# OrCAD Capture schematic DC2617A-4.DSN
size Custom; title: ISO SPI AND ISOLATED CAN ARDUINO BOARD; rev: 4; company: TM
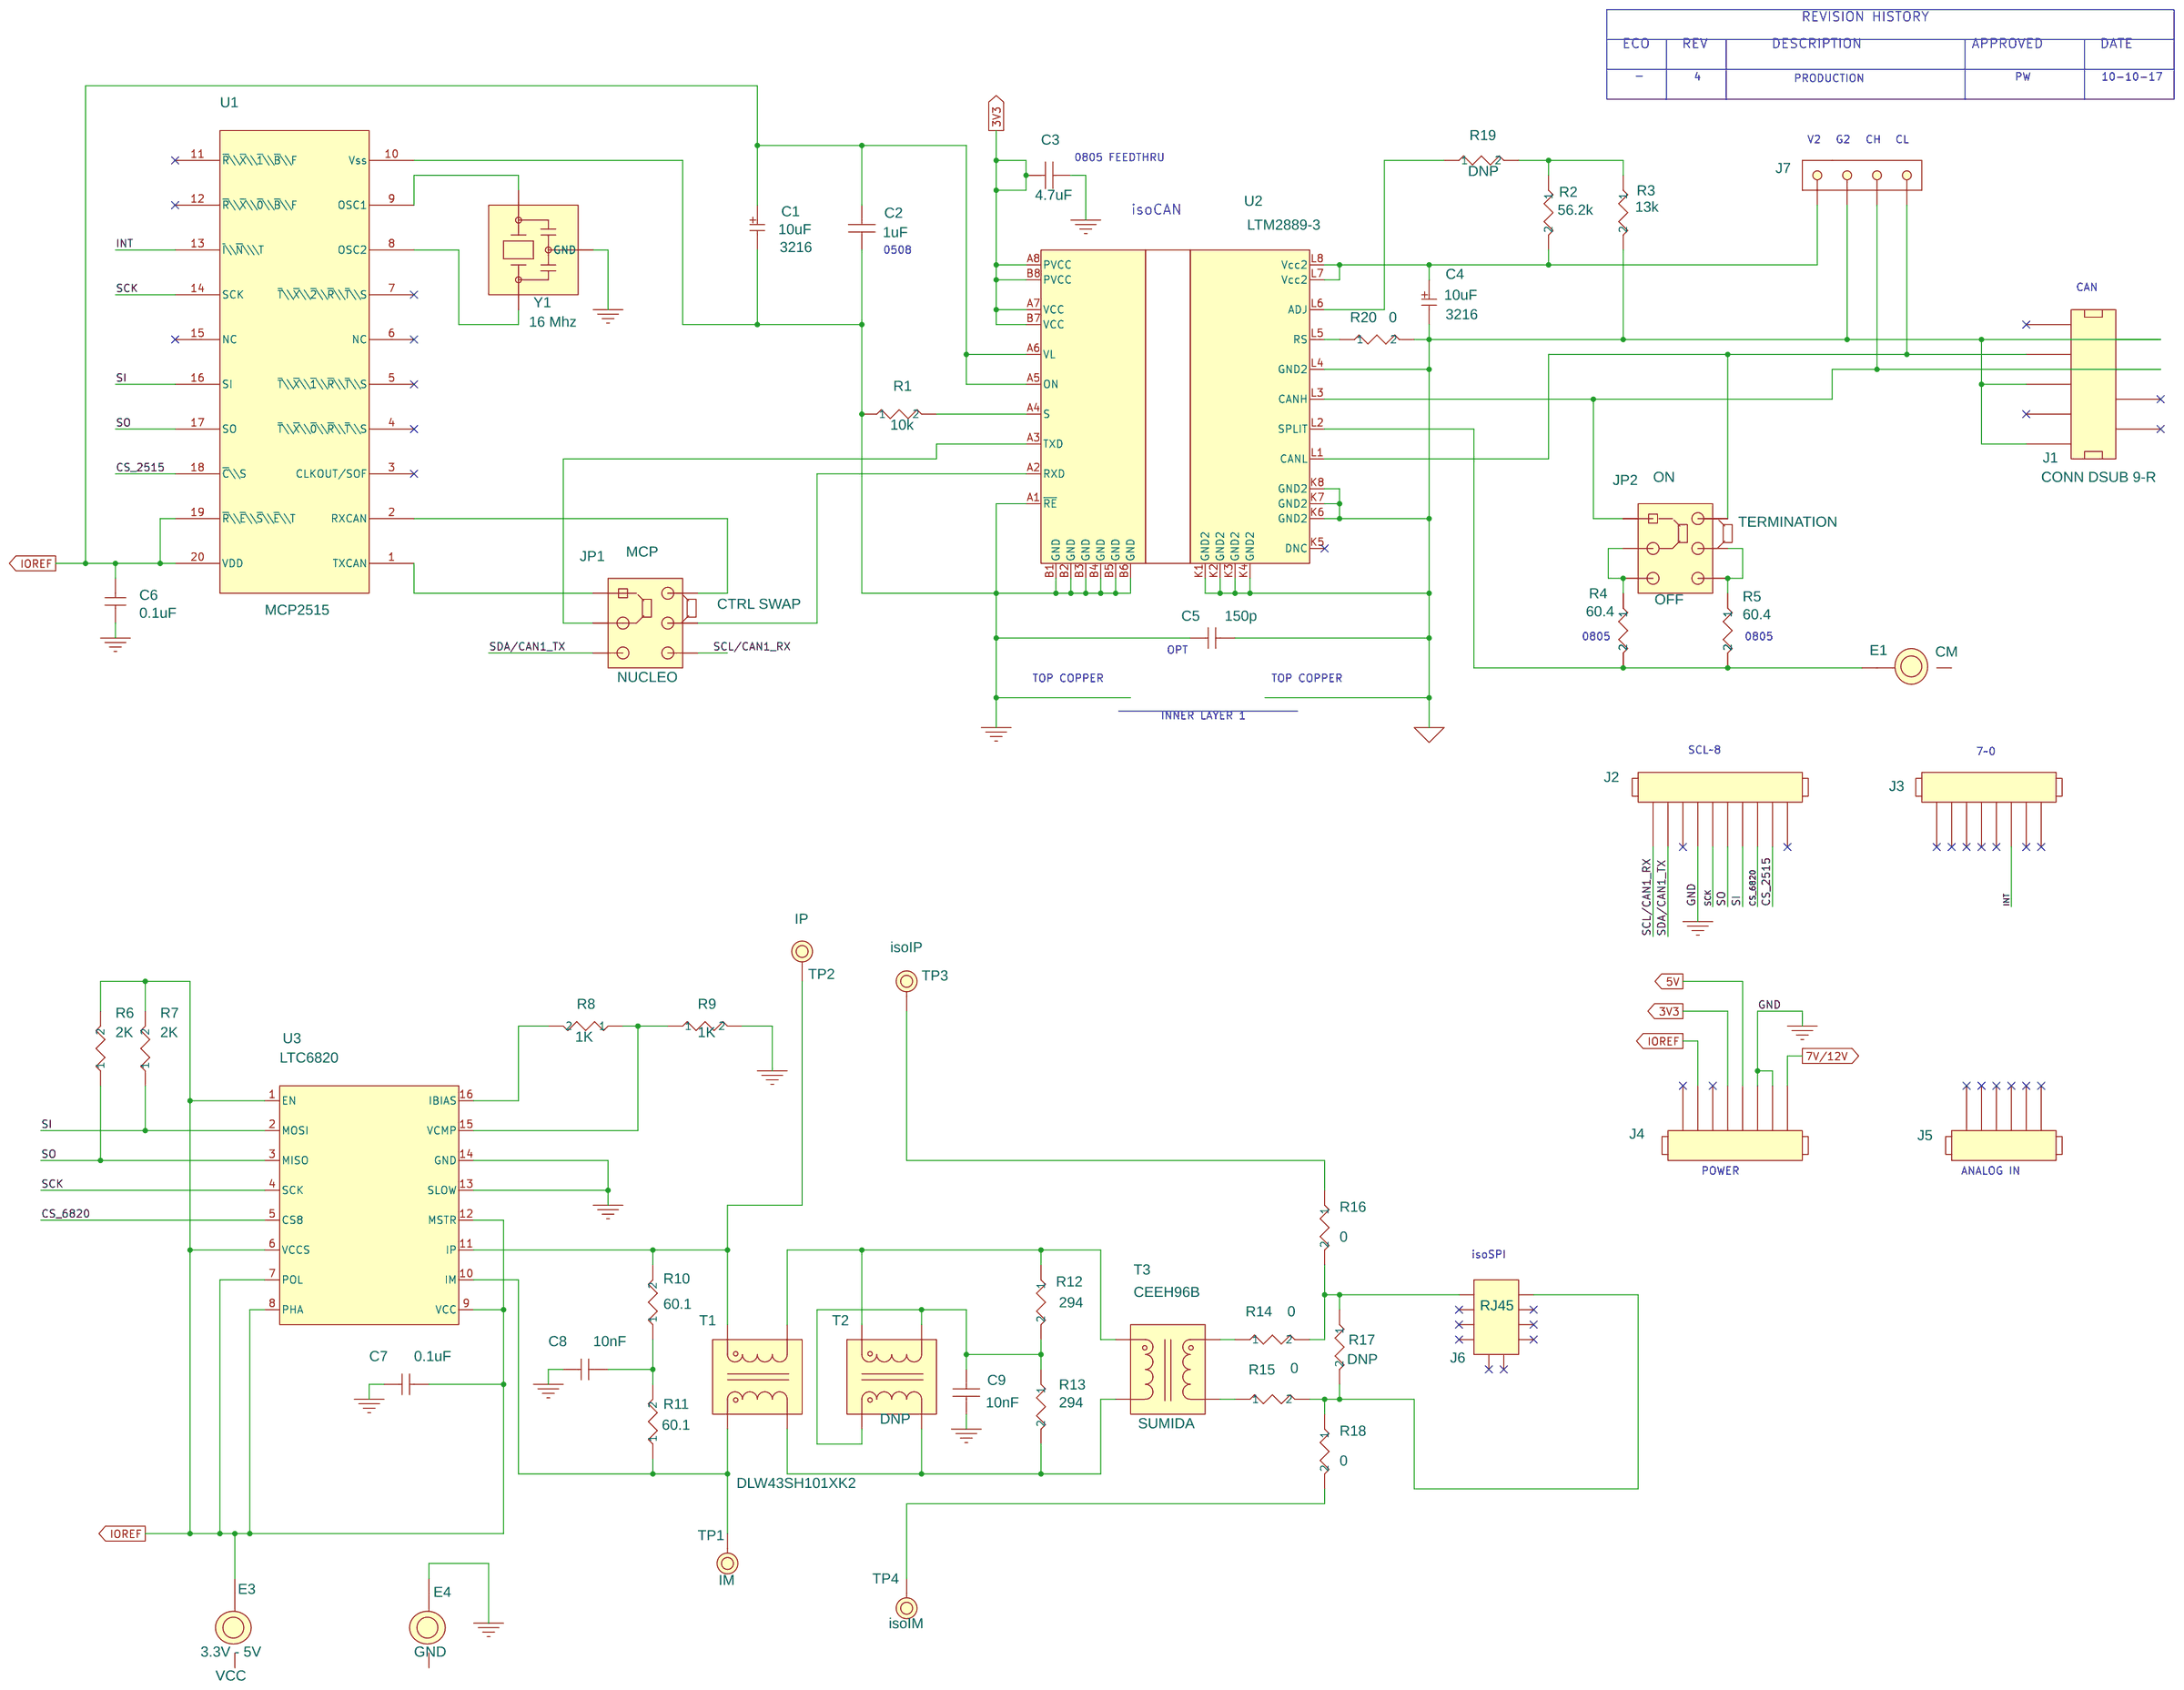
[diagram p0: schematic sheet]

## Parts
C1  10uF  [3216/1206]
C2  1uF  [MURATA-LLL219R71A105MA01L]
C3  4.7uF  [MURATA-NFM21P]
C4  10uF  [3216/1206]
C5  150p  [VISHAY-VY1_SERIES]
C6  0.1uF  [0603]
C7  0.1uF  [0603]
C8  10nF  [0603]
C9  10nF  [0603]
E1  CM  [MILLMAX-2308-2]
E3  VCC  [MILLMAX-2308-2]
E4  GND  [MILLMAX-2308-2]
J1  CONN DSUB 9-R  [CON-D-SUB9-SHIELDED]
J2  SQ POST HEADER SKT 10PIN  [SIP-10P-ARDUINO]
J3  SQ POST HEADER SKT 8PIN  [SIP-8P-ARDUINO]
J4  SQ POST HEADER SKT 8PIN  [SIP-8P-ARDUINO]
J5  SQ POST HEADER SKT 6PIN  [SIP-6P-ARDUINO]
J6  RJ45  [RJ45]
J7  HDR.  [HDR-TSW-104-07-L-S]
JP1  3 Pins 2mm Ctrs.  [HDR2X3-0.1]
JP2  3 Pins 2mm Ctrs.  [HDR2X3-0.1]
R1  10k  [0603]
R2  56.2k  [0603]
R3  13k  [0603]
R4  60.4  [0805]
R5  60.4  [0805]
R6  2K  [0603]
R7  2K  [0603]
R8  1K  [0603]
R9  1K  [0603]
R10  60.1  [0603]
R11  60.1  [0603]
R12  294  [0603]
R13  294  [0603]
R14  0  [0603]
R15  0  [0603]
R16  0  [0603]
R17  DNP  [0603]
R18  0  [0603]
R19  DNP  [0603]
R20  0  [0603]
T1  DLW43SH101XK2  [TRANS-DLW43S]
T2  DNP  [TRANS-DLW43S]
T3  CEEH96B  [TRANS-CEEH96B]
TP1  5019  [TP]
TP2  5019  [TP]
TP3  5019  [TP]
TP4  5019  [TP]
U1  MCP2515  [MICROCHIP-SO20-TSSOP]
U2  LTM2889-3  [LTM-BGA-32-1851]
U3  LTC6820  [MS16]
XJP18  2mm Ctrs.
XJP19  2mm Ctrs.
XJP20  2mm Ctrs.
XJP21  2mm Ctrs.
Y1  16 Mhz  [MURATA-CSTCE]

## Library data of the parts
C1 C4 = C_elect_0: Voltage: 3216
C2 = CAP_NP_1_v2: CAP, 0402 10nF 10% 16V X7R; Part Number: AVX 0402YC103KAT2A
C3 = CAP_NP_0: CAP, 0402 10nF 10% 16V X7R; Part Number: AVX 0402YC103KAT2A
C5-C8 = CAP-NP: CAP, 0603 0.01uF; Part Number: TDK C1608X7R1E104K
C9 = CAP_NP_1: CAP, 0603 100nF 10% 25V X7R; Part Number: MURATA GCM188R71E104KA57D
E1 E4 = E_13
E3 = E_13: VOLTAGE: 3.3V - 5V
J1 = CONN_DSUB_9-R
J2 = SQ_POST_HEADER_SKT_10PIN
J3 J4 = SQ_POST_HEADER_SKT_8PIN
J5 = SQ_POST_HEADER_SKT_6PIN
J6 = HEADER_16_8
J7 = HDR1X4: CONN.,HDR.,MALE,1x4,2.54mm,THT, STR; CLASS: IO; Manufacturer: SAMTEC; Manufacturer PN: TSW-104-07-L-S; PART_NUMBER: 250-0580
JP1 = Commcon2802s03g2_0: 10th Part Field: MCP; 11th Part Field: NUCLEO; 12th Part Field: RUN; 9th Part Field: CTRL SWAP
JP2 = Commcon2802s03g2_0: 10th Part Field: ON; 11th Part Field: OFF; 12th Part Field: RUN; 9th Part Field: TERMINATION
R1 = R_7: RES, 0603 4.99K OHMS  1% 1/10W; 5%: 1%; Part Number: NIC NRC06F4991TRF; Tol: 1%
R2 = R_8: RES, 0603 4.99K OHMS  1% 1/10W; 5%: 1%; Part Number: NIC NRC06F4991TRF; Tol: 1%
R3 = R_19: RES, 0603 4.99K OHMS  1% 1/10W; 5%: 1%; Part Number: NIC NRC06F4991TRF; Tol: 1%
R4 = R_1: RES, 0603 4.99K OHMS  1% 1/10W; 5%: 1%; Part Number: NIC NRC06F4991TRF; Tol: 1%
R5 = R: RES, 0603 4.99K OHMS  1% 1/10W; 5%: 1%; Part Number: NIC NRC06F4991TRF; Tol: 1%
R6 = R_14: RES, 0603 4.99K OHMS  1% 1/10W; 5%: 1%; Part Number: NIC NRC06F4991TRF; Tol: 1%
R7 = R_5: RES, 0603 4.99K OHMS  1% 1/10W; 5%: 1%; Part Number: NIC NRC06F4991TRF; Tol: 1%
R8 = R_16: RES, 0603 4.99K OHMS  1% 1/10W; 5%: 1%; Part Number: NIC NRC06F4991TRF; Tol: 1%
R9 = R_3: RES, 0603 4.99K OHMS  1% 1/10W; 5%: 1%; Part Number: NIC NRC06F4991TRF; Tol: 1%
R10 = R_11: RES, 0603 4.99K OHMS  1% 1/10W; 5%: 1%; Part Number: NIC NRC06F4991TRF; Tol: 1%
R11 = R_12: RES, 0603 4.99K OHMS  1% 1/10W; 5%: 1%; Part Number: NIC NRC06F4991TRF; Tol: 1%
R12 = R_13: RES, 0603 100 OHMS 1% 1/10W; Part Number: NIC NRC06F1000TRF; Tol: 1%
R13 = R_10: RES, 0603 100 OHMS 1% 1/10W; Part Number: NIC NRC06F1000TRF; Tol: 1%
R14 = R_6: RES, 0603 100 OHMS 1% 1/10W; Part Number: NIC NRC06F1000TRF; Tol: 1%
R15 = R_4: RES, 0603 100 OHMS 1% 1/10W; Part Number: NIC NRC06F1000TRF; Tol: 1%
R16 = R_9: RES, 0603 100 OHMS 1% 1/10W; Part Number: NIC NRC06F1000TRF; Tol: 1%
R17 = R_2: RES, 0603 100 OHMS 1% 1/10W; Part Number: NIC NRC06F1000TRF; Tol: 1%
R18 = R_15: RES, 0603 100 OHMS 1% 1/10W; Part Number: NIC NRC06F1000TRF; Tol: 1%
R19 = R_18: RES, 0603 4.99K OHMS  1% 1/10W; 5%: 1%; Part Number: NIC NRC06F4991TRF; Tol: 1%
R20 = R_17: RES, 0603 100 OHMS 1% 1/10W; Part Number: NIC NRC06F1000TRF; Tol: 1%
T1 T2 = TRANS-PA0950_22: 4TH PART FIELD: PULSE,; 5TH PART FIELD: PA08xx; 7TH PART FIELD: TRANS.,
T3 = TRANS-PA0950_10: 4TH PART FIELD: SUMIDA; 5TH PART FIELD: PA08xx; 7TH PART FIELD: TRANS.,
TP1 = TP-GENERIC: PC TEST POINT MINI SMD; CLASS: DISCRETE; Label: IM; Manufacturer: Keystone Electronics; PART_NUMBER: TP2
TP2 = TP-GENERIC: PC TEST POINT MINI SMD; CLASS: DISCRETE; Label: IP; Manufacturer: Keystone Electronics; PART_NUMBER: TMP-1572
TP3 = TP-GENERIC: PC TEST POINT MINI SMD; CLASS: DISCRETE; Label: isoIP; Manufacturer: Keystone Electronics; PART_NUMBER: TMP-1572
TP4 = TP-GENERIC: PC TEST POINT MINI SMD; CLASS: DISCRETE; Label: isoIM; Manufacturer: Keystone Electronics; PART_NUMBER: TP2
U1 = MCP2515_1
U2 = LTM2889CY_4
U3 = LTC6820_0
XJP18-XJP21 = CommconCCIJ2MM-138G
Y1 = 16_MHZ_RESONATOR

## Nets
3V3: C3.1(INPUT) C3.3(OUTPUT) J4.4 U2.A7(VCC) U2.A8(PVCC) U2.B7(VCC) U2.B8(PVCC)
5V: J4.5
7V/12V: J4.8
GND: C1.2(-) C2.2 C3.2(GND) C5.1 C6.1 C7.1 C8.1 C9.1 E4.1(A) J2.7 J4.6 J4.7 R1.1 R9.2 U1.10(Vss) U2.A1(~{RE}) U2.B1(GND) U2.B2(GND) U2.B3(GND) U2.B4(GND) U2.B5(GND) U2.B6(GND) U3.13(SLOW) U3.14(GND) Y1.2(GND)
GND_SIGNAL: C4.2(-) C5.2 J1.3 J1.5 J1.6 J7.3 R3.2 R20.2 U2.K1(GND2) U2.K2(GND2) U2.K3(GND2) U2.K4(GND2) U2.K6(GND2) U2.K7(GND2) U2.K8(GND2) U2.L4(GND2)
CS_2515: J2.2 U1.18(~{C}\\S)
CS_6820: J2.3 U3.5(CS8)
INT: J3.3 U1.13(~{I}\\~{N}\\\T)
IOREF: C1.1(+) C2.1 C6.2 C7.2 E3.1(A) J4.2 R6.2 R7.2 U1.19(~{R}\\~{E}\\~{S}\\~{E}\\T) U1.20(VDD) U2.A5(ON) U2.A6(VL) U3.1(EN) U3.6(VCCS) U3.7(POL) U3.8(PHA) U3.9(VCC) U3.12(MSTR)
SCK: J2.6 U1.14(SCK) U3.4(SCK)
SCL/CAN1_RX: J2.10 JP1.6
SDA/CAN1_TX: J2.9 JP1.5
SI: J2.4 R7.1 U1.16(SI) U3.2(MOSI)
SO: J2.5 R6.1 U1.17(SO) U3.3(MISO)
N04568: R13.2 T1.3 T2.3 T3.4
N04752: J6.1 R15.2 R17.2 R18.1
N04796: R11.1 T1.4 TP1.1 U3.10(IM)
N05048: R10.2 T1.1 TP2.1 U3.11(IP)
N05256: C8.2 R10.1 R11.2
N05312: R8.2 U3.16(IBIAS)
N05708: R8.1 R9.1 U3.15(VCMP)
N05796: R15.1 T3.1
N05910: R12.1 T1.2 T2.1 T3.3
N05986: C9.2 R12.2 R13.1 T2.2 T2.4
N06182: R14.1 T3.2
N06186: J6.2 R14.2 R16.2 R17.1
N06414: R16.1 TP3.1
N06430: R18.2 TP4.1
N08378: R19.1 U2.L6(ADJ)
N11583: C4.1(+) J7.4 R2.2 U2.L7(Vcc2) U2.L8(Vcc2)
N12335: E1.1(A) R4.2 R5.2 U2.L2(SPLIT)
N12444: R2.1 R3.1 R19.2
N13029: J1.2 J7.1 JP2.2 U2.L1(CANL)
N13053: J1.7 J7.2 JP2.1 U2.L3(CANH)
N13822: JP2.3 JP2.5 R4.1
N13830: JP2.4 JP2.6 R5.1
N48166: JP1.2 U1.2(RXCAN)
N49968: JP1.4 U2.A2(RXD)
N50090: JP1.1 U1.1(TXCAN)
N50095: JP1.3 U2.A3(TXD)
N162907: U1.9(OSC1) Y1.3
N208727: R20.1 U2.L5(RS)
N16680170: R1.2 U2.A4(S)
N16707870: U1.8(OSC2) Y1.1

Not connected (* = marked no-connect by the designer): J1 1* 4* 8* 9*; J2 1* 8*; J3 1* 2* 4* 5* 6* 7* 8*; J4 1* 3*; J5 1* 2* 3* 4* 5* 6*; J6 3* 4* 5* 6* 7* 8* 11* 12*; U1 3(CLKOUT/SOF)* 4(~{T}\\~{X}\\~{0}\\~{R}\\~{T}\\S)* 5(~{T}\\~{X}\\~{1}\\~{R}\\~{T}\\S)* 6(NC)* 7(~{T}\\~{X}\\~{2}\\~{R}\\~{T}\\S)* 11(~{R}\\~{X}\\~{1}\\~{B}\\F)* 12(~{R}\\~{X}\\~{0}\\~{B}\\F)* 15(NC)*; U2 K5(DNC)*

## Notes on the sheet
- REVISION HISTORY
- ECO
- REV
- DESCRIPTION
- APPROVED
- DATE
- -
- 4
- PW
- 10-10-17
- PRODUCTION
- V2
- G2
- CH
- CL
- 0805 FEEDTHRU
- isoCAN
- 0508
- CAN
- 0805
- 0805
- OPT
- TOP COPPER
- TOP COPPER
- INNER LAYER 1
- SCL~8
- 7~0
- POWER
- ANALOG IN
- isoSPI
